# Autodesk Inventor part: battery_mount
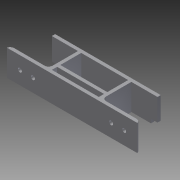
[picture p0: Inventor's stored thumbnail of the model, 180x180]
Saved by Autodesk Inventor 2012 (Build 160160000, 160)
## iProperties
Created: 2011-06
Part Number: battery_mount
Document SubType Name: Modeling
Designer: Bruce
Density: 1 g/cm^3
Material: Default
Author: Bruce
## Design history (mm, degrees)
sketch "Sketch1"
  geometry: L1 (0, 0)-(0, 32.736); L2 (-100, 0)-(-100, 33.252); L3 (0, 0)-(-100, 0); L4 (6.601, 9)-(-97.844, 9); L5 (-68, 9)-(-68, 39.614); L6 (-32, 9)-(-32, 40.171); L7 (-70.218, 25)-(-18.872, 25); L8 (-68, 9)-(-68, 25); L9 (-68, 25)-(-32, 25); L10 (-32, 25)-(-32, 9); L11 (-32, 9)-(-68, 9); L12 (-70.5, 2.5)-(-70.5, 27.5); L13 (-70.5, 27.5)-(-29.5, 27.5); L14 (-29.5, 2.5)-(-29.5, 27.5); L15 (-116.846, 2.5)-(34.537, 2.5); L16 (-100, 0)-(-100, 2.5); L17 (-100, 2.5)-(-70.5, 2.5); L18 (0, 0)-(0, 2.5); L19 (0, 2.5)-(-29.5, 2.5); L20 (-32, 2.5)-(-68, 2.5); L21 (-68, 2.5)-(-68, 6.5); L22 (-68, 6.5)-(-32, 6.5); L23 (-32, 6.5)-(-32, 2.5); 4 further points
  constraints: 46 end point, 21 point on line, 6 perpendicular, 5 parallel, 4 collinear, 1 horizontal, 1 vertical
  dimensions: "mount_width" = 100 distance between parallel lines of L1 L2; "d1" = 9 distance between parallel lines of L3 L4; "d2" = 36 distance between parallel lines of L6 L5 (= battery_width); "d3" = 16 distance between parallel lines of L4 L7 (= battery_thickness); "d4" = 32 distance between parallel lines of L1 L6 (= -0.5 x battery_width + 0.5 x mount_width); "d5" = 2.5 distance between parallel lines of L8 L12 (= structural_cover); "d6" = 2.5 distance between parallel lines of L6 L14 (= structural_cover); "d7" = 2.5 distance between parallel lines of L9 L13 (= structural_cover); "d21" = 2.5 distance between parallel lines of L3 L15 (= structural_cover); "d22" = 2.5 distance between parallel lines of L11 L22 (= structural_cover); "d23" = 2.5 distance between parallel lines of L23 L14 (= structural_cover); "d24" = 2.5 distance between parallel lines of L12 L21 (= structural_cover)
extrude "Extrusion1" new body sketch "Sketch1" distance "d8" = 20 (= arm_width + 2 x structural_cover); taper "d9" = 0 deg
sketch "Sketch2"
  geometry: L1 (0, 0)-(0, 20) reference; L2 (100, 0)-(100, 20) reference; L3 (100, 10)-(0, 10); C1 r 1.5 at (90, 10); C2 r 1.5 at (80, 10); C3 r 1.5 at (20, 10); C4 r 1.5 at (10, 10)
  constraints: 4 centre point, 4 point on line, 2 end point, 2 midpoint
  dimensions: "d10" = 3 diameter of C1 (= arm_fixing_bolt); "d11" = 3 diameter of C2 (= arm_fixing_bolt); "d12" = 3 diameter of C3 (= arm_fixing_bolt); "d13" = 3 diameter of C4 (= arm_fixing_bolt); "d14" = 10 distance from line of C1.centre L2 (= arm_fixing_spacing); "d15" = 10 distance of C2.centre C1.centre (= arm_fixing_spacing); "d16" = 10 distance from line of L1 C4.centre (= arm_fixing_spacing); "d17" = 10 distance of C4.centre C3.centre (= arm_fixing_spacing)
extrude "Extrusion2" cut sketch "Sketch2" distance "d18" = 10 (= arm_fixing_spacing); taper "d19" = 0 deg
fillet "Fillet1" dims "d20" = 3
sketch "Sketch3"
  geometry: L1 (20, -22)-(20, 0) reference; L2 (0, 0)-(20, 0); L3 (20, 0)-(20, -2.5); L4 (20, -2.5)-(0, -2.5); L5 (0, -2.5)-(0, 0); 1 further point
  constraints: 8 end point, 2 parallel, 1 horizontal, 1 perpendicular, 1 point on line
  dimensions: "d25" = 2.5 distance of L2.end L3.end (= structural_cover)
sketch "Sketch4"
  geometry: L1 (20, 0)-(20, -22) reference; L2 (0, 0)-(20, 0); L3 (20, 0)-(20, -2.5); L4 (20, -2.5)-(0, -2.5); L5 (0, -2.5)-(0, 0); 1 further point
  constraints: 8 end point, 2 parallel, 1 horizontal, 1 perpendicular, 1 point on line
  dimensions: "d26" = 2.5 distance of L2.end L3.end (= structural_cover)
extrude "Extrusion3" join sketch "Sketch4" distance "d27" = 20 (= landing_gear_thickness + landing_gear_offset); taper "d28" = 0 deg
extrude "Extrusion4" join sketch "Sketch3" distance "d29" = 20 (= landing_gear_thickness + landing_gear_offset); taper "d30" = 0 deg
sketch "Sketch5"
  geometry: L1 (0, 0)-(20, 0) reference; L2 (0, -2.5)-(0, 0) reference; L3 (0, -2.5)-(3, -2.5); L4 (3, -2.5)-(3, 0); L5 (3, 0)-(0, 0); L6 (0, 0)-(0, -2.5); 1 further point
  constraints: 8 end point, 2 parallel, 1 horizontal, 1 perpendicular, 1 point on line
  dimensions: "d31" = 3 distance of L5.end L4.end
sketch "Sketch6"
  geometry: L1 (0, 0)-(20, 0) reference; L2 (20, -2.5)-(17, -2.5); L3 (17, -2.5)-(17, 0); L4 (17, 0)-(20, 0); L5 (20, 0)-(20, -2.5); 1 further point
  constraints: 8 end point, 2 parallel, 1 horizontal, 1 perpendicular, 1 point on line
  dimensions: "d32" = 3 distance of L3.end L4.end
extrude "Extrusion5" cut sketch "Sketch6" distance "d33" = 5 (= landing_gear_thickness); taper "d34" = 0 deg
extrude "Extrusion6" cut sketch "Sketch5" distance "d35" = 5 (= landing_gear_thickness); taper "d36" = 0 deg
body "Solid1"
other parameters: "structural_cover" = 2.5 [user parameter; used in 10 equation terms], "arm_fixing_bolt" = 3 [user parameter; used in 4 equation terms], "arm_fixing_spacing" = 10 [user parameter; used in 5 equation terms], "landing_gear_thickness" = 5 [user parameter; used in 4 equation terms], "battery_width" = 36 [user parameter; used in 2 equation terms], "battery_thickness" = 16 [user parameter; used in 1 equation term], "landing_gear_offset" = 15 [user parameter; used in 2 equation terms], "arm_width" = 15 [user parameter; used in 1 equation term]
